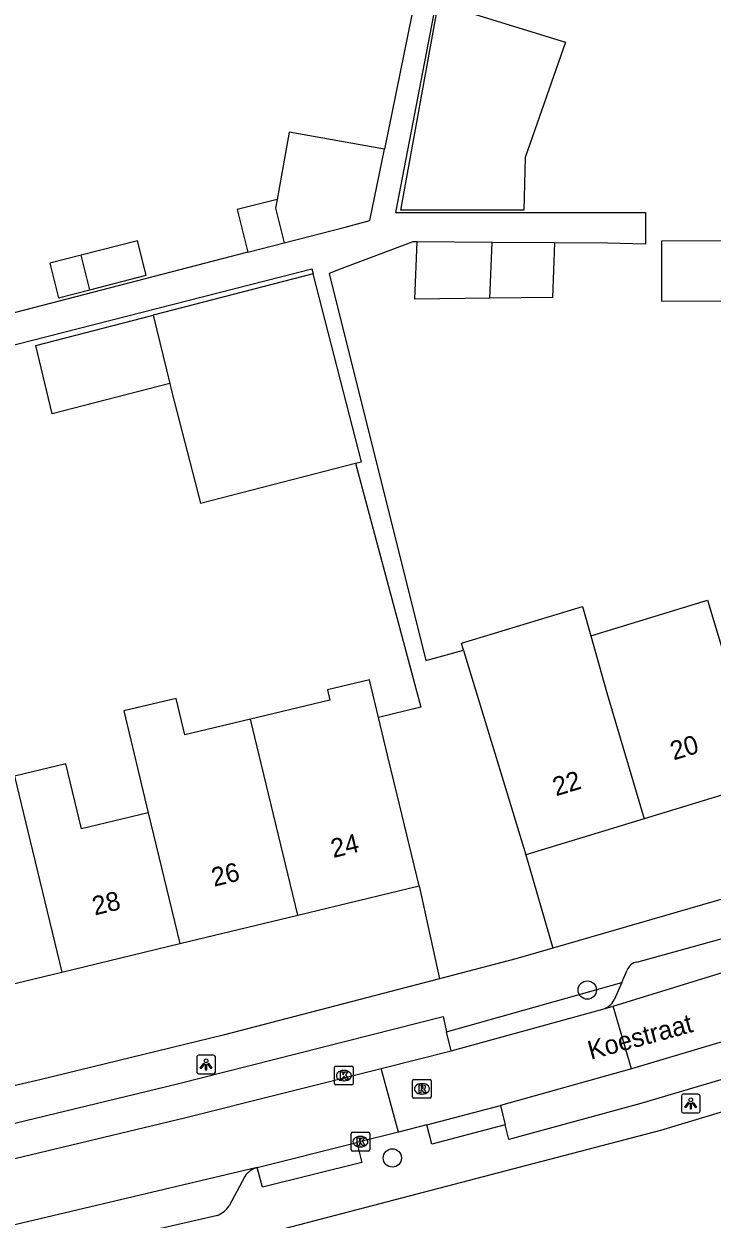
# Model space of a CAD drawing. Extents: x 163010 to 163853, y 382793 to 383982.
# Drawn here: x 163214.8 to 163251.5, y 383784.1 to 383847.9 of the extents above; entities that cross this region are included whole.
import ezdxf

# ---------------------------------------------------------------- set-up
doc = ezdxf.new("R2010")
doc.units = 0
for name, color, linetype in [('IMGEO_Boom', 7, 'Continuous'), ('IMGEO_Kolk', 7, 'Continuous'), ('IMGEO_Lichtpunt', 7, 'Continuous'), ('IMGEO_Openbare_ruimte_label', 7, 'Continuous'), ('IMGEO_Pand', 7, 'Continuous'), ('IMGEO_Pand_nummerreeks', 7, 'Continuous'), ('IMGEO_Rijbaan_lokaal_open', 7, 'Continuous'), ('IMGEO_Rioolput', 7, 'Continuous'), ('IMGEO_Voetpad_open', 7, 'Continuous')]:
    doc.layers.add(name, color=color, linetype=linetype)

msp = doc.modelspace()

# ---------------------------------------------------------------- linework, layer by layer
at = {"layer": 'IMGEO_Boom'}
for centre in [(163244.88, 383796.316), (163234.474, 383787.353)]:
    msp.add_circle(centre, 0.489, dxfattribs=at)
at = {"layer": 'IMGEO_Kolk'}
for p, q in [((163231.386, 383791.323), (163231.386, 383792.175)), ((163231.461, 383792.249), (163232.313, 383792.249)), ((163231.874, 383792.029), (163231.899, 383792.029)), ((163232.387, 383792.175), (163232.387, 383791.323)), ((163232.313, 383791.249), (163231.461, 383791.249)), ((163231.897, 383791.469), (163231.872, 383791.469)), ((163232.269, 383787.796), (163232.269, 383788.648)), ((163232.344, 383788.722), (163233.196, 383788.722)), ((163232.757, 383788.502), (163232.782, 383788.502)), ((163233.27, 383788.648), (163233.27, 383787.796)), ((163232.78, 383787.942), (163232.755, 383787.942)), ((163233.196, 383787.722), (163232.344, 383787.722))]:
    msp.add_line(p, q, dxfattribs=at)
for points in [[(163231.386, 383791.323), (163231.386, 383792.175)], [(163231.461, 383792.249), (163232.313, 383792.249)], [(163231.707, 383791.949), (163231.83, 383791.949), (163231.83, 383791.798), (163231.96, 383791.949), (163232.124, 383791.949), (163231.978, 383791.798), (163232.131, 383791.549), (163231.979, 383791.549), (163231.894, 383791.713), (163231.83, 383791.646), (163231.83, 383791.549), (163231.707, 383791.549), (163231.707, 383791.949)], [(163232.387, 383792.175), (163232.387, 383791.323)], [(163232.313, 383791.249), (163231.461, 383791.249)], [(163232.269, 383787.796), (163232.269, 383788.648)], [(163232.344, 383788.722), (163233.196, 383788.722)], [(163233.27, 383788.648), (163233.27, 383787.796)], [(163232.59, 383788.422), (163232.713, 383788.422), (163232.713, 383788.271), (163232.843, 383788.422), (163233.007, 383788.422), (163232.861, 383788.271), (163233.014, 383788.022), (163232.862, 383788.022), (163232.777, 383788.186), (163232.713, 383788.119), (163232.713, 383788.022), (163232.59, 383788.022), (163232.59, 383788.422)], [(163233.196, 383787.722), (163232.344, 383787.722)]]:
    msp.add_lwpolyline(points, dxfattribs=at)
for centre, start, end in [((163231.463, 383792.173), 91.55205, 178.44795), ((163231.463, 383792.173), 91.55205, 178.44795), ((163232.311, 383792.173), 1.55205, 88.44795), ((163232.311, 383792.173), 1.55205, 88.44795), ((163231.463, 383791.325), 181.55205, 268.44795), ((163231.463, 383791.325), 181.55205, 268.44795), ((163232.311, 383791.325), 271.55205, 358.44795), ((163232.311, 383791.325), 271.55205, 358.44795), ((163232.346, 383788.646), 91.55205, 178.44795), ((163232.346, 383788.646), 91.55205, 178.44795), ((163233.194, 383788.646), 1.55205, 88.44795), ((163233.194, 383788.646), 1.55205, 88.44795), ((163232.346, 383787.798), 181.55205, 268.44795), ((163232.346, 383787.798), 181.55205, 268.44795), ((163233.194, 383787.798), 271.55205, 358.44795), ((163233.194, 383787.798), 271.55205, 358.44795)]:
    msp.add_arc(centre, 0.0765, start, end, dxfattribs=at)
for centre, major_axis, ratio, start_param, end_param in [((163231.873, 383791.749), (-0.387, 0.002), 0.722429, 4.712389, 7.853982), ((163231.898, 383791.749), (-0.39, 0.002), 0.717154, 1.570796, 4.712389), ((163232.756, 383788.222), (-0.387, 0.002), 0.722429, 4.712389, 7.853982), ((163232.781, 383788.222), (-0.39, 0.002), 0.717154, 1.570796, 4.712389)]:
    msp.add_ellipse(centre, major_axis=major_axis, ratio=ratio, start_param=start_param, end_param=end_param, dxfattribs=at)
at = {"layer": 'IMGEO_Lichtpunt'}
for p, q in [((163224.031, 383792.744), (163224.031, 383791.937)), ((163224.031, 383792.744), (163224.031, 383791.937)), ((163224.933, 383792.839), (163224.125, 383792.839)), ((163224.933, 383792.839), (163224.125, 383792.839)), ((163225.027, 383791.937), (163225.027, 383792.744)), ((163225.027, 383791.937), (163225.027, 383792.744)), ((163224.125, 383791.843), (163224.933, 383791.843)), ((163224.125, 383791.843), (163224.933, 383791.843)), ((163249.909, 383790.658), (163249.909, 383789.851)), ((163249.909, 383790.658), (163249.909, 383789.851)), ((163250.811, 383790.753), (163250.003, 383790.753)), ((163250.811, 383790.753), (163250.003, 383790.753)), ((163250.905, 383789.851), (163250.905, 383790.658)), ((163250.905, 383789.851), (163250.905, 383790.658)), ((163250.003, 383789.757), (163250.811, 383789.757)), ((163250.003, 383789.757), (163250.811, 383789.757))]:
    msp.add_line(p, q, dxfattribs=at)
for points in [[(163224.405, 383792.408), (163224.444, 383792.38), (163224.256, 383792.118), (163224.218, 383792.145), (163224.405, 383792.408)], [(163224.507, 383792.36), (163224.554, 383792.36), (163224.554, 383792.038), (163224.507, 383792.038), (163224.507, 383792.36)], [(163224.617, 383792.38), (163224.655, 383792.407), (163224.842, 383792.145), (163224.803, 383792.117), (163224.617, 383792.38)], [(163250.283, 383790.322), (163250.322, 383790.294), (163250.134, 383790.032), (163250.096, 383790.059), (163250.283, 383790.322)], [(163250.385, 383790.274), (163250.432, 383790.274), (163250.432, 383789.952), (163250.385, 383789.952), (163250.385, 383790.274)], [(163250.495, 383790.294), (163250.533, 383790.321), (163250.72, 383790.059), (163250.681, 383790.031), (163250.495, 383790.294)]]:
    msp.add_lwpolyline(points, dxfattribs=at)
for centre in [(163224.53, 383792.542), (163250.408, 383790.456)]:
    msp.add_circle(centre, 0.0994, dxfattribs=at)
for centre, start, end in [((163224.125, 383792.744), 90, 180), ((163224.125, 383792.744), 90, 180), ((163224.933, 383792.744), 0, 90), ((163224.933, 383792.744), 0, 90), ((163224.125, 383791.937), 180, 270), ((163224.125, 383791.937), 180, 270), ((163224.933, 383791.937), 270, 0), ((163224.933, 383791.937), 270, 360), ((163250.003, 383790.658), 90, 180), ((163250.003, 383790.658), 90, 180), ((163250.811, 383790.658), 0, 90), ((163250.811, 383790.658), 0, 90), ((163250.003, 383789.851), 180, 270), ((163250.003, 383789.851), 180, 270), ((163250.811, 383789.851), 270, 0), ((163250.811, 383789.851), 270, 360)]:
    msp.add_arc(centre, 0.0946, start, end, dxfattribs=at)
at = {"layer": 'IMGEO_Pand'}
for points in [[(163243.718, 383846.922), (163241.568, 383840.758), (163241.548, 383840.045), (163241.487, 383837.952), (163235.608, 383837.952), (163234.931, 383837.952), (163236.933, 383849.009), (163237.574, 383848.812), (163238.228, 383848.611), (163243.718, 383846.922)], [(163234.053, 383841.193), (163228.975, 383842.112), (163228.325, 383838.521)], [(163228.706, 383836.208), (163231.952, 383837.044), (163233.278, 383837.386), (163234.053, 383841.193)], [(163228.325, 383838.521), (163226.197, 383837.972), (163226.302, 383837.557), (163226.766, 383835.709)], [(163228.325, 383838.521), (163228.241, 383838.057), (163228.706, 383836.208)], [(163218.328, 383833.691), (163221.336, 383834.467), (163220.861, 383836.313), (163217.863, 383835.541)], [(163252.979, 383836.315), (163248.852, 383836.292), (163248.838, 383833.082), (163252.965, 383833.102)], [(163226.766, 383835.709), (163228.706, 383836.208)], [(163239.683, 383833.246), (163235.674, 383833.203), (163235.794, 383836.252)], [(163239.8, 383836.223), (163235.794, 383836.252)], [(163239.683, 383833.246), (163239.8, 383836.223)], [(163243.141, 383836.199), (163243.027, 383833.282), (163239.683, 383833.246)], [(163243.141, 383836.199), (163239.8, 383836.223)], [(163217.863, 383835.541), (163216.184, 383835.108), (163216.659, 383833.261), (163218.328, 383833.691)], [(163218.328, 383833.691), (163217.863, 383835.541)], [(163230.249, 383834.539), (163221.708, 383832.338)], [(163232.509, 383824.436), (163232.831, 383824.519), (163230.249, 383834.539)], [(163222.589, 383828.684), (163216.314, 383827.067), (163215.433, 383830.721), (163221.708, 383832.338)], [(163221.708, 383832.338), (163222.589, 383828.684)], [(163222.589, 383828.684), (163222.681, 383828.303), (163224.227, 383822.302), (163232.509, 383824.436)], [(163238.274, 383814.451), (163238.16, 383814.825), (163244.627, 383816.797), (163245.069, 383815.229)], [(163245.069, 383815.229), (163251.306, 383817.131), (163252.19, 383814.169)], [(163245.069, 383815.229), (163245.93, 383812.176), (163247.926, 383805.456)], [(163238.274, 383814.451), (163238.348, 383814.21), (163239.562, 383810.234), (163240.149, 383808.312), (163241.608, 383803.529)], [(163233.735, 383810.867), (163233.252, 383812.87), (163231.017, 383812.332), (163231.146, 383811.796), (163226.905, 383810.774)], [(163226.905, 383810.774), (163223.404, 383809.93), (163222.933, 383811.886), (163220.135, 383811.211), (163221.443, 383805.782)], [(163235.902, 383801.874), (163234.73, 383806.735), (163234.218, 383808.86), (163233.735, 383810.867)], [(163229.426, 383800.313), (163227.742, 383807.3), (163226.905, 383810.774)], [(163221.443, 383805.782), (163217.881, 383804.924), (163217.044, 383808.397), (163214.307, 383807.737)], [(163214.307, 383807.737), (163215.144, 383804.264), (163216.828, 383797.277)], [(163254.217, 383807.375), (163247.926, 383805.456)], [(163221.443, 383805.782), (163223.127, 383798.795)], [(163247.926, 383805.456), (163241.608, 383803.529)], [(163229.426, 383800.313), (163235.902, 383801.874)], [(163223.127, 383798.795), (163229.426, 383800.313)], [(163216.828, 383797.277), (163223.127, 383798.795)], [(163210.528, 383795.759), (163216.828, 383797.277)]]:
    msp.add_lwpolyline(points, dxfattribs=at)
at = {"layer": 'IMGEO_Rijbaan_lokaal_open'}
for points in [[(163246.261, 383795.456), (163274.68, 383804.205)], [(163264.509, 383797.251), (163247.238, 383792.104)], [(163237.612, 383793.063), (163245.721, 383795.302)], [(163245.721, 383795.302), (163246.261, 383795.456)], [(163247.238, 383792.104), (163246.261, 383795.456)], [(163233.88, 383792.129), (163237.612, 383793.063)], [(163208.237, 383785.865), (163208.724, 383785.982), (163223.378, 383789.502), (163233.88, 383792.129)], [(163234.8, 383788.729), (163233.88, 383792.129)], [(163247.238, 383792.104), (163240.244, 383790.15)], [(163236.313, 383789.124), (163240.244, 383790.15)], [(163236.313, 383789.124), (163234.8, 383788.729)], [(163234.8, 383788.729), (163232.58, 383788.173)], [(163227.264, 383786.84), (163232.58, 383788.173)], [(163227.264, 383786.84), (163204.753, 383781.529), (163195.101, 383779.504), (163194.621, 383779.405)]]:
    msp.add_lwpolyline(points, dxfattribs=at)
at = {"layer": 'IMGEO_Rioolput'}
for p, q in [((163235.552, 383790.615), (163235.552, 383791.467)), ((163235.627, 383791.541), (163236.479, 383791.541)), ((163236.04, 383791.321), (163236.065, 383791.321)), ((163236.553, 383791.467), (163236.553, 383790.615)), ((163236.479, 383790.541), (163235.627, 383790.541)), ((163236.063, 383790.761), (163236.038, 383790.761))]:
    msp.add_line(p, q, dxfattribs=at)
for points in [[(163235.552, 383790.615), (163235.552, 383791.467)], [(163235.627, 383791.541), (163236.479, 383791.541)], [(163236.141, 383791.239), (163235.889, 383791.241), (163235.889, 383790.841)], [(163235.889, 383790.841), (163236.013, 383790.841), (163236.013, 383791.003), (163236.024, 383791.003)], [(163236.067, 383791.16), (163236.013, 383791.16), (163236.013, 383791.079)], [(163236.013, 383791.079), (163236.065, 383791.079)], [(163236.553, 383791.467), (163236.553, 383790.615)], [(163236.479, 383790.541), (163235.627, 383790.541)], [(163236.071, 383790.974), (163236.142, 383790.841), (163236.282, 383790.841), (163236.217, 383790.967)]]:
    msp.add_lwpolyline(points, dxfattribs=at)
for centre, radius, start, end in [((163235.629, 383791.465), 0.0765, 91.55205, 178.44795), ((163235.629, 383791.465), 0.0765, 91.55205, 178.44795), ((163236.023, 383790.95), 0.0533, 26.02933, 88.69889), ((163236.049, 383791.268), 0.19, 274.7715, 282.96867), ((163236.073, 383791.064), 0.0964, 77.00612, 93.18647), ((163236.087, 383791.121), 0.0378, 276.66336, 79.67722), ((163236.14, 383791.129), 0.109, 350.36119, 89.41601), ((163236.138, 383791.129), 0.112, 277.58423, 350.98172), ((163236.122, 383790.914), 0.108, 29.51342, 73.79051), ((163236.477, 383791.465), 0.0765, 1.55205, 88.44795), ((163236.477, 383791.465), 0.0765, 1.55205, 88.44795), ((163235.629, 383790.617), 0.0765, 181.55205, 268.44795), ((163235.629, 383790.617), 0.0765, 181.55205, 268.44795), ((163236.477, 383790.617), 0.0765, 271.55205, 358.44795), ((163236.477, 383790.617), 0.0765, 271.55205, 358.44795)]:
    msp.add_arc(centre, radius, start, end, dxfattribs=at)
for centre, major_axis, ratio, start_param, end_param in [((163236.039, 383791.041), (-0.387, 0.002), 0.722429, 4.712389, 7.853982), ((163236.064, 383791.041), (-0.39, 0.002), 0.717154, 1.570796, 4.712389)]:
    msp.add_ellipse(centre, major_axis=major_axis, ratio=ratio, start_param=start_param, end_param=end_param, dxfattribs=at)
at = {"layer": 'IMGEO_Voetpad_open'}
for points in [[(163241.573, 383873.797), (163234.649, 383837.824), (163247.996, 383837.824), (163247.996, 383836.131), (163245.959, 383836.178), (163243.141, 383836.199)], [(163237.408, 383857.66), (163234.053, 383841.193)], [(163226.766, 383835.709), (163202.41, 383829.385), (163202.836, 383827.843), (163230.18, 383834.809), (163230.249, 383834.539)], [(163235.794, 383836.252), (163235.576, 383836.254), (163231.783, 383834.826), (163231.098, 383834.558), (163236.27, 383813.908), (163238.274, 383814.451)], [(163232.509, 383824.436), (163235.989, 383811.41), (163233.735, 383810.867)], [(163274.697, 383808.286), (163273.465, 383807.841), (163257.671, 383802.78), (163243.046, 383798.554)], [(163247.534, 383797.81), (163253.96, 383799.574), (163259.473, 383801.257), (163271.55, 383805.172)], [(163241.608, 383803.529), (163243.046, 383798.554)], [(163235.902, 383801.874), (163237, 383796.921)], [(163119.034, 383764.505), (163142.448, 383767.592), (163175.747, 383772.352), (163205.449, 383778.073), (163224.77, 383782.549), (163248.813, 383788.839), (163265.635, 383793.903), (163278.283, 383798.072), (163287.084, 383801.323)], [(163243.046, 383798.554), (163241.06, 383797.98), (163237, 383796.921)], [(163246.72, 383796.718), (163247.02, 383797.377)], [(163237, 383796.921), (163225.435, 383793.906), (163215.661, 383791.514), (163199.832, 383787.879), (163185.721, 383785.063), (163168.413, 383782.104), (163153.288, 383779.812), (163138.415, 383777.914)], [(163237.374, 383794.092), (163246.72, 383796.718)], [(163246.72, 383796.718), (163246.325, 383795.787)], [(163210.555, 383788.295), (163223.007, 383791.308), (163237.185, 383794.907), (163237.374, 383794.092)], [(163262.442, 383794.639), (163262.174, 383794.528), (163247.742, 383790.26), (163240.694, 383788.336), (163240.497, 383789.129)], [(163237.612, 383793.063), (163237.374, 383794.092)], [(163240.244, 383790.15), (163240.497, 383789.129)], [(163240.497, 383789.129), (163236.584, 383788.081), (163236.313, 383789.124)], [(163232.58, 383788.173), (163232.854, 383787.112), (163227.535, 383785.788), (163227.264, 383786.84)], [(163226.598, 383786.362), (163225.755, 383784.793)], [(163225.148, 383784.285), (163205.13, 383779.692), (163197.682, 383778.077), (163197.349, 383778.052)]]:
    msp.add_lwpolyline(points, dxfattribs=at)
for centre, radius, start, end in [((163247.604, 383797.205), 0.609, 96.60695, 163.61546), ((163245.433, 383796.28), 1.019, 286.43275, 331.0948), ((163227.6, 383785.669), 1.218, 106.0063, 145.32905), ((163224.591, 383785.568), 1.398, 293.48697, 326.36514)]:
    msp.add_arc(centre, radius, start, end, dxfattribs=at)

# ---------------------------------------------------------------- texts
at = {"layer": 'IMGEO_Openbare_ruimte_label'}
msp.add_text('Koestraat', height=1, rotation=15.24507, dxfattribs=at).set_placement((163245.068, 383792.59))
at = {"layer": 'IMGEO_Pand_nummerreeks'}
for s, rotation, p in [('20', 16.95955, (163249.492, 383808.569)), ('22', 16.95955, (163243.215, 383806.654)), ('24', 13.55045, (163231.324, 383803.363)), ('26', 13.54968, (163224.954, 383801.828)), ('28', 13.54968, (163218.588, 383800.294))]:
    msp.add_text(s, height=1, rotation=rotation, dxfattribs=at).set_placement(p)

doc.saveas('drawing.dxf')
